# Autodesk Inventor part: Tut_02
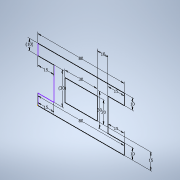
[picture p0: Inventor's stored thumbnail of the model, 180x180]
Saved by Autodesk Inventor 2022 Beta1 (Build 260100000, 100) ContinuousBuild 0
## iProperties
Created: 2019-02
Part Number: Tut_02
Material: Generic
Document SubType Name: Modeling
Designer: LENOVO-CADCIM
Density: 1 g/cm^3
Appearance: Default
Author: LENOVO-CADCIM
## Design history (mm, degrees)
sketch "Sketch1"
  geometry: L1 (0, 0)-(80, 0); L2 (80, 0)-(80, 10); L3 (80, 10)-(65, 10); L4 (65, 10)-(65, 40); L5 (65, 40)-(80, 40); L6 (80, 40)-(80, 50); L7 (80, 50)-(0, 50); L8 (0, 50)-(0, 40); L9 (0, 40)-(15, 40); L10 (15, 40)-(15, 10); L11 (15, 10)-(0, 10); L12 (0, 10)-(0, 0); L13 (25, 15)-(55, 15); L14 (55, 15)-(55, 35); L15 (55, 35)-(25, 35); L16 (25, 35)-(25, 15); 1 further point
  constraints: 32 end point, 6 perpendicular, 6 point on line, 2 horizontal, 2 parallel, 1 coincident, 1 collinear
  dimensions: "d0" = 80 distance of L1.start L1.end; "d1" = 10 distance of L1.end L2.end; "d2" = 15 distance of L2.end L3.end; "d3" = 30 distance of L3.end L4.end; "d4" = 15 distance of L4.end L5.end; "d5" = 10 distance of L5.end L6.end; "d6" = 80 distance of L6.end L7.end; "d7" = 10 distance of L7.end L8.end (derived); "d8" = 15 distance of L8.end L9.end; "d9" = 30 distance of L9.end L10.end (derived); "d10" = 15 distance of L10.end L11.end; "d11" = 30 distance of L15.end L14.end; "d12" = 20 distance of L14.end L13.end; "d14" = 15 distance between parallel lines of L13 L1; "d15" = 10 distance between parallel lines of L14 L4
